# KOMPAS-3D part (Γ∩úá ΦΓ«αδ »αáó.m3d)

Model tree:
1. Эскиз:1
2. Операция выдавливания:1
     Расстояние 1 = 22; Расстояние 2 = 3
3. Эскиз:2
4. Операция выдавливания:2
     Расстояние 1 = 2; Расстояние 2 = 3
5. Эскиз:3
6. Операция выдавливания:3
     Расстояние 1 = 5; Расстояние 2 = 3
7. Эскиз:4
8. Операция выдавливания:4
     Расстояние 1 = 0.1; Расстояние 2 = 3
9. Эскиз:5
10. Операция выдавливания:5
     Расстояние 1 = 1.5; Расстояние 2 = 0.5
11. Эскиз:6
12. Операция выдавливания:6
     Расстояние 1 = 2; Расстояние 2 = 0.5
13. Ломаная:2
14. Перпендикулярная плоскость:2
15. Эскиз:13
16. Кинематическая операция:2
     Толщина стенки 1 = 1; Толщина стенки 2 = 1
17. Смещенная плоскость:1
     Расстояние = 2
18. Эскиз:14
19. Операция выдавливания:12
     Расстояние 1 = 2; Расстояние 2 = 0.5
20. Эскиз:15
21. Операция выдавливания:13
     Расстояние 1 = 3; Расстояние 2 = 0.5
22. Эскиз:16
23. Операция выдавливания:14
     Расстояние 1 = 2; Расстояние 2 = 0.5
24. Зеркальное отражение:1

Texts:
  stalker61
  Сплав АЛ8  ГОСТ 1583-93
